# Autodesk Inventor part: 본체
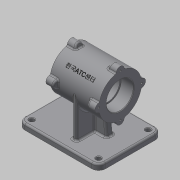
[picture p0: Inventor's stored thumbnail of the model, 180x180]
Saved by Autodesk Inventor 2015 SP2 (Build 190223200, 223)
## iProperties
Created: 2015-12
Part Number: 본체
Material: 일반
Document SubType Name: Modeling
Designer: AMC
Density: 1 g/cm^3
Appearance: 기본값
Author: AMC
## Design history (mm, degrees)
sketch "스케치1"
  geometry: L1 (-80, 55)-(60, 55); L2 (60, 55)-(60, -55); L3 (60, -55)-(-80, -55); L4 (-80, -55)-(-80, 55); 1 further point
  constraints: 8 end point, 2 parallel, 1 horizontal, 1 perpendicular
  dimensions: "d0" = 140 distance of L1.start L1.end; "d1" = 110 distance of L1.end L2.end; "d2" = 55 distance from line of point (0, 0) L1; "d3" = 80 distance from line of L4 point (0, 0)
extrude "돌출1" new body sketch "스케치1" distance "d4" = 10; taper "d5" = 0 deg
sketch "스케치2"
  geometry: 1 further point
sketch "스케치3"
  geometry: L1 (55, 0)-(-55, 0) reference; C1 r 37 at (0, 80); 2 further points
  constraints: 1 centre point, 1 midpoint, 1 vertical alignment
  dimensions: "d6" = 74 diameter of C1; "d7" = 80 distance from line of L1 C1.centre
extrude "돌출2" join sketch "스케치3" stored distance "d8" = 85; taper "d9" = 0 deg
sketch "스케치4"
  geometry: L1 (-4, 37)-(4, 37); L2 (4, 37)-(4, -37); L3 (4, -37)-(-4, -37); L4 (-4, -37)-(-4, 37); L5 (-4, 37)-(4, -37); L6 (4, 37)-(-4, -37); 1 further point
  constraints: 12 end point, 2 midpoint, 2 parallel, 1 horizontal, 1 perpendicular
  dimensions: "d11" = 8 distance of L1.start L1.end; "d12" = 74 distance of L1.end L2.end
extrude "돌출3" join sketch "스케치4" distance "d13" = 70; taper "d14" = 0 deg
sketch "스케치5"
  geometry: L1 (-25, 10)-(-21.08, 41.923); L2 (80, 10)-(-60, 10) reference; 1 further point
  constraints: 2 end point, 1 point on line
  dimensions: "d15" = 97 deg angle of L2 L1; "d16" = 25 horizontal distance of L1.start point (0, 0)
feature "리브1" sketch "스케치5" dims "d17" = 1, "d18" = 12, "d19" = 0, "d20" = 0, "d21" = 1, "d22" = 1
sketch "스케치6"
  geometry: L1 (-42.5, 103.5)-(-20.5, 103.5); L2 (-20.5, 103.5)-(-20.5, 101); L3 (-20.5, 101)-(20.5, 101); L4 (20.5, 101)-(20.5, 103.5); L5 (20.5, 103.5)-(42.5, 103.5); L6 (42.5, 103.5)-(42.5, 80); L7 (42.5, 80)-(-42.5, 80); L8 (-42.5, 80)-(-42.5, 103.5); L9 (-60, 0)-(80, 0) reference; L10 (-42.5, 117)-(-42.5, 43) reference; L11 (42.5, 43)-(42.5, 117) reference; 1 further point
  constraints: 16 end point, 3 perpendicular, 2 collinear, 2 horizontal, 2 parallel, 1 point on line, 1 vertical
  dimensions: "d23" = 47 diameter of L5 L7; "d24" = 42 diameter of L3 L7; "d25" = 80 distance between parallel lines of L9 L7; "d26" = 22 distance of L4.end L5.end; "d27" = 22 distance of L1.start L1.end
revolve "회전1" sketch "스케치6" stored, may be unused: angle "d28" = 90 deg
fillet "모깎기1" dims "d29" = 0.3
chamfer "모따기1" distance "d30" = 1; stored, may be unused: second distance "d31" = 2, angle "d32" = 45 deg
sketch "스케치7"
  geometry: C1 r 7 at (-37, 0); 2 further points
  constraints: 2 horizontal alignment, 1 centre point, 1 other
  dimensions: "d33" = 14 diameter of C1
extrude "돌출4" join sketch "스케치7" distance "d34" = 15; taper "d35" = 0 deg
sketch "스케치8"
  geometry: L1 (42.5, 117)-(-27.5, 117) reference; L2 (-27.5, 116.338)-(-27.5, 124) reference; L3 (-42.5, 124)-(-27.5, 124) reference; L4 (-27.5, 117)-(-30.048, 124); L5 (-54.623, 80)-(55.411, 80); L6 (-60, 0)-(80, 0) reference; 1 further point
  constraints: 4 end point, 1 horizontal, 1 point on line
  dimensions: "d36" = 110 deg angle of L1 L4; "d37" = 80 distance between parallel lines of L6 L5
revolve "회전2" stored, may be unused: angle "d38" = 30 deg
fillet "모깎기2" dims "d39" = 3
sketch "스케치9"
  geometry: A1 r 37 centre (80, 0) between (115.862, 9.104) and (89.104, 35.863) reference; 3 further points
  constraints: 2 horizontal alignment, 4 other
hole "구멍1" sketch "스케치9" at (117, 0) diameter "d43" = 3.242; stored, may be unused: countersink angle "d47" = 90 deg, drill point angle "d49" = 118 deg; dims "d44" = 9, "d45" = 4, "d46" = 2, "d48" = 11
fillet "모깎기3" dims "d53" = 3
fillet "모깎기4" dims "d54" = 3
fillet "모깎기5" dims "d55" = 3
fillet "모깎기6" dims "d56" = 12
hole "구멍2" diameter "d59" = 8; stored, may be unused: countersink angle "d63" = 90 deg, drill point angle "d65" = 118 deg; dims "d57" = 10, "d58" = 10, "d60" = 9, "d61" = 4, "d62" = 2, "d64" = 11
chamfer "모따기2" distance "d72" = 1; stored, may be unused: second distance "d73" = 2, angle "d74" = 45 deg
fillet "모깎기7" dims "d75" = 3
node "작업 평면2"
  node "작업 평면1"
sketch "스케치10"
  geometry: L1 (-25, 3.5)-(25, 3.5); L2 (25, 3.5)-(25, -3.5); L3 (25, -3.5)-(-25, -3.5); L4 (-25, -3.5)-(-25, 3.5); L5 (-25, 0)-(25, 0); L6 (0, 3.5)-(0, -3.5); L7 (-108, 0)-(88, 0) reference; 1 further point
  constraints: 4 end point, 4 midpoint, 1 collinear, 1 point on line, 2 other
  dimensions: "d77" = 50 distance of L1.start L1.end; "d78" = 7 distance of L1.end L2.end
feature "엠보싱1" sketch "스케치10" dims "d0" = 140, "d1" = 110, "d2" = 55, "d3" = 80, "d11" = 8, "d12" = 74, "d79" = 0.5, "d80" = 0
node "솔리드1"
mirror "대칭1"
mirror "대칭2"
pattern_circular "원형 패턴1" dims "d41" = 360 deg
pattern_circular "원형 패턴2" dims angle "d51" = 360 deg
mirror "대칭3"
pattern_linear "직사각형 패턴1" dims "d68" = 116, "d71" = 86
node "작업축2"
other parameters: "d76" = -45 deg
